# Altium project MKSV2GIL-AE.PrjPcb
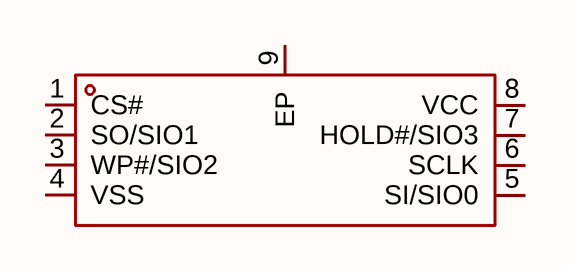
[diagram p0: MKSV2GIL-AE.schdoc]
1 sheet, 1 parts. Net scope: global (net labels, ports and power ports of the same name join across sheets).

## Sheet MKSV2GIL-AE.schdoc
size 127 x 101 mm

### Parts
U?  mksv2gil-ae  [WSON-8_L8.0-W6.0-P1.27-BL-EP-1]  (value not drawn)

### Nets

Not connected (* = marked no-connect by the designer): U? 1(CS#) 2(SO/SIO1) 3(WP#/SIO2) 4(VSS) 5(SI/SIO0) 6(SCLK) 7(HOLD#/SIO3) 8(VCC) 9(EP)

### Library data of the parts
U? = mksv2gil-ae: 存储容量:2Gbit;时钟频率(fc):104MHz;工作电压:2.7V~3.6V;; Manufacturer: MK(米客方德); AddInBom: yes; Memory Size: 2Gbit; Interface: SPI; Clock Frequency: 104MHz; Page Program time (TPP): 600us; Block Erase Time(tBE): 3ms; Data Retention - TDR (Year): 10年; Standby Supply Current: 65uA; Program / Erase Cycles: 10万次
